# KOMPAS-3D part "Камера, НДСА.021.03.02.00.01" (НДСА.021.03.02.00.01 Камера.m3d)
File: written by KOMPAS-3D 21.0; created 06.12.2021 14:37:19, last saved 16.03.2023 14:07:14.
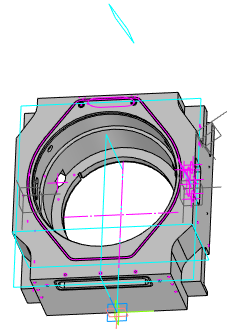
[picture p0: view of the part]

Document properties: Полное имя файла: C:\Users\korychko\Desktop\PLM\НДСА.021.03.02.00.01 Камера.m3d

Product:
- Part/product: Камера  | designation НДСА.021.03.02.00.01
    Материал: АМг6  ГОСТ 4784-2019 (density 2640 kg/m3)
    Масса: 77.159778
    additional columns: <item xmlns="http://appius.ru/pdm" xmlns:xs="http://www.w3.org/2001/XMLSchema" x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; <item xmlns="http://appius.ru/pdm" xmlns:xs="http://www.w3.org/2001/XMLSchema" x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; <item xmlns="http://appius.ru/pdm" xmlns:xs="http://www.w3.org/2001/XMLSchema" x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
    source file: НДСА.021.03.02.00.01 Камера.cdw

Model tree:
1. Эскиз:1
2. Элемент выдавливания:1
     Расстояние 1 = 232
3. Эскиз:2  (with: Элемент выдавливания:1)
4. Элемент выдавливания:2
     Расстояние 2 = 9
5. Эскиз:3  (with: Элемент выдавливания:2)
6. Элемент выдавливания:3
     Расстояние 2 = 75
7. Эскиз:4  (with: Элемент выдавливания:3)
8. Элемент выдавливания:4
     Расстояние 2 = 118
9. Эскиз:5  (with: Элемент выдавливания:4)
10. Элемент выдавливания:5
     Расстояние 2 = 30
11. Средняя плоскость:1  (with: Элемент выдавливания:1)
12. Эскиз:9  (with: Элемент выдавливания:1)
13. Элемент выдавливания:7
     Расстояние 2 = 159
14. Эскиз:11  (with: Элемент выдавливания:1)
15. Элемент выдавливания:8
     Расстояние 2 = 70
16. Эскиз:12  (with: Элемент выдавливания:1, Элемент выдавливания:8, Элемент выдавливания:5)
17. Отверстие:10  (with: Элемент выдавливания:1)  (labels: M6)
     Глубина выреза = 15; Диаметр отверстия = 4.91747; Угол конуса дна = 118; Расстояние 1 = 27.9101; Расстояние 2 = 119.75
18. M6  (with: Элемент выдавливания:1)  (labels: M6; cil0_24705-2004 coarse)
     Длина резьбы = 10; Шаг резьбы = 1; Номинальный диаметр резьбы = 6
19. Массив по концентрической сетке:1  (with: Отверстие:10)  (labels: M6)  (2 pattern instances)
20. Отверстие:10  (labels: M6)
21. Зеркальный массив:1
22. Экземпляр ( 1 )
23. Экземпляр ( 2 )  (with: Массив по концентрической сетке:1, Экземпляр ( 1 ), Отверстие:10)
24. Экземпляр ( 2 )  (with: Отверстие:10)
25. Экземпляр ( 3 )  (with: Отверстие:10)
26. Эскиз:16  (with: Элемент выдавливания:1, Элемент выдавливания:7)
27. Отверстие:13  (with: Элемент выдавливания:1)  (labels: M8)
     Глубина выреза = 20; Диаметр отверстия = 6.64684; Угол конуса дна = 118; Расстояние 1 = 212; Расстояние 2 = 419
28. M8  (with: Элемент выдавливания:1)  (labels: cil0_24705-2004 coarse)
     Длина резьбы = 15; Шаг резьбы = 1.25; Номинальный диаметр резьбы = 8
29. Отверстие:14  (with: Элемент выдавливания:1, M8)  (labels: M8; cil0_24705-2004 coarse)
     Глубина выреза = 20; Диаметр отверстия = 6.64684; Угол конуса дна = 118; Расстояние 1 = 164; Расстояние 2 = 419; Длина резьбы = 15; Шаг резьбы = 1.25; Номинальный диаметр резьбы = 8
30. Отверстие:15  (with: Элемент выдавливания:1, M8)  (labels: M8; cil0_24705-2004 coarse)
     Глубина выреза = 20; Диаметр отверстия = 6.64684; Угол конуса дна = 118; Расстояние 1 = 116; Расстояние 2 = 419; Длина резьбы = 15; Шаг резьбы = 1.25; Номинальный диаметр резьбы = 8
31. Зеркальный массив:3  (with: Экземпляр ( 1 ), Экземпляр ( 2 ), Отверстие:13)
32. Отверстие:14
33. Отверстие:15
34. Эскиз:17  (with: Элемент выдавливания:1, Элемент выдавливания:7)
35. Эскиз:18  (with: Элемент выдавливания:1)
36. Элемент выдавливания:11
     Расстояние 2 = 20
37. Эскиз:19  (with: Элемент выдавливания:11)
38. Отверстие:16  (with: Элемент выдавливания:11)  (labels: M10)
     Глубина выреза = 26; Диаметр отверстия = 8.3762; Угол конуса дна = 118; Расстояние 1 = -30; Расстояние 2 = 95
39. M10  (with: Элемент выдавливания:11)  (labels: cil0_24705-2004 coarse)
     Длина резьбы = 20; Шаг резьбы = 1.5; Номинальный диаметр резьбы = 10
40. Отверстие:17  (with: Элемент выдавливания:11, M10)  (labels: M10; cil0_24705-2004 coarse)
     Глубина выреза = 26; Диаметр отверстия = 8.3762; Угол конуса дна = 118; Расстояние 1 = -30; Расстояние 2 = 13; Длина резьбы = 20; Шаг резьбы = 1.5; Номинальный диаметр резьбы = 10
41. Зеркальный массив:4  (with: Экземпляр ( 1 ), Экземпляр ( 2 ), Элемент выдавливания:11, Отверстие:16)
42. Отверстие:17
43. Сечение:3
44. Смещенная плоскость:1  (with: Элемент выдавливания:1)
     Расстояние = -44
45. Эскиз:21
46. Эскиз:22  (with: Элемент выдавливания:1)
47. Эскиз:23  (with: Элемент выдавливания:1, Элемент выдавливания:7)
48. Элемент выдавливания:12
     Расстояние 2 = 10
49. Эскиз:24  (with: Элемент выдавливания:1)
50. Смещенная плоскость:2  (with: Элемент выдавливания:1)
     Расстояние = -140
51. Эскиз:31  (with: Элемент выдавливания:1)
52. Элемент выдавливания:16
     Расстояние 2 = 232
53. Эскиз:32  (with: Элемент выдавливания:1)
54. Элемент выдавливания:17
     Расстояние 2 = 140
55. Эскиз:33  (with: Элемент выдавливания:1)
56. Эскиз:34
57. Элемент по траектории:3
58. Эскиз:35  (with: Элемент выдавливания:1)
59. Отверстие:20  (with: Элемент выдавливания:1)
     Глубина выреза = 27; Диаметр отверстия = 4.5; Угол конуса дна = 118; Расстояние 1 = 216.5; Расстояние 2 = 198
60. Отверстие:21  (with: Элемент выдавливания:1)  (labels: M3)
     Глубина выреза = 14; Диаметр отверстия = 2.45873; Угол конуса дна = 118; Расстояние 1 = 224.5; Расстояние 2 = 206
61. M3  (with: Элемент выдавливания:1)  (labels: M3; cil0_24705-2004 coarse)
     Длина резьбы = 10; Шаг резьбы = 0.5; Номинальный диаметр резьбы = 3
62. Отверстие:22  (with: Элемент выдавливания:1, M3)  (labels: M3; cil0_24705-2004 coarse)
     Глубина выреза = 14; Диаметр отверстия = 2.45873; Угол конуса дна = 118; Расстояние 1 = 208.5; Расстояние 2 = 206; Длина резьбы = 10; Шаг резьбы = 0.5; Номинальный диаметр резьбы = 3
63. Отверстие:23  (with: Элемент выдавливания:1, M3)  (labels: M3; cil0_24705-2004 coarse)
     Глубина выреза = 14; Диаметр отверстия = 2.45873; Угол конуса дна = 118; Расстояние 1 = 224.5; Расстояние 2 = 190; Длина резьбы = 10; Шаг резьбы = 0.5; Номинальный диаметр резьбы = 3
64. Отверстие:24  (with: Элемент выдавливания:1, M3)  (labels: M3; cil0_24705-2004 coarse)
     Глубина выреза = 14; Диаметр отверстия = 2.45873; Угол конуса дна = 118; Расстояние 1 = 208.5; Расстояние 2 = 190; Длина резьбы = 10; Шаг резьбы = 0.5; Номинальный диаметр резьбы = 3
65. Зеркальный массив:6  (with: Экземпляр ( 1 ), Экземпляр ( 2 ), Отверстие:20, Отверстие:21)
66. Отверстие:22
67. Отверстие:23
68. Отверстие:24
69. Эскиз:36  (with: Элемент выдавливания:1)
70. Элемент выдавливания:18
     Расстояние 2 = 2.5; Угол 2 = 24
71. Скругление:12  (with: Элемент выдавливания:18)
     Радиус = 0.8
72. Скругление:13  (with: Элемент выдавливания:18)
     Радиус = 0.25
73. Эскиз:37  (with: Элемент выдавливания:1, Скругление:13)
74. Отверстие:25  (with: Элемент выдавливания:1)
     Глубина выреза = 18; Диаметр отверстия = 4.5; Угол конуса дна = 118; Расстояние 1 = -70; Расстояние 2 = -497
75. Отверстие:26  (with: Элемент выдавливания:1)
     Глубина выреза = 18; Диаметр отверстия = 4.5; Угол конуса дна = 118; Расстояние 1 = 70; Расстояние 2 = -497
76. Эскиз:38  (with: Элемент выдавливания:1)
77. Элемент выдавливания:19
     Расстояние 2 = 14
78. Эскиз:39  (with: Элемент выдавливания:1)
79. Элемент выдавливания:20
     Расстояние 2 = 24
80. Эскиз:40  (with: Элемент выдавливания:1)
81. Элемент выдавливания:21  (with: Элемент выдавливания:3)
     Расстояние 2 = 50
82. Эскиз:41  (with: Элемент выдавливания:19)
83. Отверстие:27  (with: Элемент выдавливания:19)  (labels: M5)
     Глубина выреза = 14; Диаметр отверстия = 4.13397; Угол конуса дна = 118; Расстояние 1 = 104; Расстояние 2 = 37
84. M5  (with: Элемент выдавливания:19)  (labels: cil0_24705-2004 coarse)
     Длина резьбы = 10; Шаг резьбы = 0.8; Номинальный диаметр резьбы = 5
85. Отверстие:28  (with: Элемент выдавливания:19, M5)  (labels: M5; cil0_24705-2004 coarse)
     Глубина выреза = 14; Диаметр отверстия = 4.13397; Угол конуса дна = 118; Расстояние 1 = 75; Расстояние 2 = 6; Длина резьбы = 10; Шаг резьбы = 0.8; Номинальный диаметр резьбы = 5
86. Отверстие:29  (with: Элемент выдавливания:19, M5)  (labels: M5; cil0_24705-2004 coarse)
     Глубина выреза = 14; Диаметр отверстия = 4.13397; Угол конуса дна = 118; Расстояние 1 = 35; Расстояние 2 = 6; Длина резьбы = 10; Шаг резьбы = 0.8; Номинальный диаметр резьбы = 5
87. Отверстие:30  (with: Элемент выдавливания:19, M5)  (labels: M5; cil0_24705-2004 coarse)
     Глубина выреза = 14; Диаметр отверстия = 4.13397; Угол конуса дна = 118; Расстояние 1 = 6; Расстояние 2 = 37; Длина резьбы = 10; Шаг резьбы = 0.8; Номинальный диаметр резьбы = 5
88. Отверстие:31  (with: Элемент выдавливания:19, M5)  (labels: M5; cil0_24705-2004 coarse)
     Глубина выреза = 14; Диаметр отверстия = 4.13397; Угол конуса дна = 118; Расстояние 1 = 35; Расстояние 2 = 68; Длина резьбы = 10; Шаг резьбы = 0.8; Номинальный диаметр резьбы = 5
89. Отверстие:32  (with: Элемент выдавливания:19, M5)  (labels: M5; cil0_24705-2004 coarse)
     Глубина выреза = 14; Диаметр отверстия = 4.13397; Угол конуса дна = 118; Расстояние 1 = 75; Расстояние 2 = 68; Длина резьбы = 10; Шаг резьбы = 0.8; Номинальный диаметр резьбы = 5
90. Эскиз:42  (with: Элемент выдавливания:20)
91. Эскиз:43
92. Элемент по траектории:4
93. Зеркальный массив:7  (with: Экземпляр ( 1 ), Экземпляр ( 2 ), Элемент выдавливания:19, Элемент выдавливания:20, Элемент выдавливания:21, Отверстие:27)
94. Отверстие:28
95. Отверстие:29
96. Отверстие:30
97. Отверстие:31
98. Отверстие:32
99. Элемент по траектории:4
100. Эскиз:44  (with: Элемент выдавливания:1)
101. Отверстие:33  (with: Элемент выдавливания:1, Элемент выдавливания:17, M8)  (labels: M8; cil0_24705-2004 coarse)
     Глубина выреза = 15; Диаметр отверстия = 6.64684; Угол конуса дна = 118; Расстояние 1 = 145.841; Расстояние 2 = 333.75; Длина резьбы = 12; Шаг резьбы = 1.25; Номинальный диаметр резьбы = 8
102. Отверстие:34  (with: Элемент выдавливания:1, Элемент выдавливания:17, M8)  (labels: M8; cil0_24705-2004 coarse)
     Глубина выреза = 15; Диаметр отверстия = 6.64684; Угол конуса дна = 118; Расстояние 1 = 79.5495; Расстояние 2 = 240; Длина резьбы = 12; Шаг резьбы = 1.25; Номинальный диаметр резьбы = 8
103. Отверстие:35  (with: Элемент выдавливания:1, Элемент выдавливания:17, M8)  (labels: M8; cil0_24705-2004 coarse)
     Глубина выреза = 15; Диаметр отверстия = 6.64684; Угол конуса дна = 118; Расстояние 1 = 13.2583; Расстояние 2 = 146.25; Длина резьбы = 12; Шаг резьбы = 1.25; Номинальный диаметр резьбы = 8
104. Эскиз:45  (with: Элемент выдавливания:1)
105. Элемент выдавливания:22  (with: Элемент выдавливания:1)
     Расстояние 2 = 232
106. Эскиз:46  (with: Элемент выдавливания:1)
107. Элемент выдавливания:23
     Расстояние 2 = 92
108. Эскиз:47  (with: Элемент выдавливания:1, Элемент выдавливания:23)
109. Эскиз:48  (with: Элемент выдавливания:1)
110. Элемент выдавливания:24
     Расстояние 2 = 70
111. Элемент выдавливания:25
     Расстояние 2 = 100
112. Эскиз:49  (with: Элемент выдавливания:25, Элемент выдавливания:3)
113. Отверстие:36  (with: Элемент выдавливания:25, Элемент выдавливания:24, M10)  (labels: M10; cil0_24705-2004 coarse)
     Глубина выреза = 20; Диаметр отверстия = 8.3762; Угол конуса дна = 118; Расстояние 1 = 75; Расстояние 2 = 35; Длина резьбы = 15; Шаг резьбы = 1.5; Номинальный диаметр резьбы = 10
114. Отверстие:37  (with: Элемент выдавливания:25, Элемент выдавливания:24, M10)  (labels: M10; cil0_24705-2004 coarse)
     Глубина выреза = 20; Диаметр отверстия = 8.3762; Угол конуса дна = 118; Расстояние 1 = 25; Расстояние 2 = 35; Длина резьбы = 15; Шаг резьбы = 1.5; Номинальный диаметр резьбы = 10
115. Зеркальный массив:8  (with: Экземпляр ( 1 ), Экземпляр ( 2 ), Отверстие:36)
116. Отверстие:37
117. Скругление:14  (with: Элемент выдавливания:25)
     Радиус = 5
118. Эскиз:50  (with: Элемент выдавливания:1, Элемент выдавливания:24)
119. Отверстие:38  (with: Элемент выдавливания:1, Элемент выдавливания:25, Элемент выдавливания:24, M5)  (labels: M5; cil0_24705-2004 coarse)
     Глубина выреза = 16; Диаметр отверстия = 4.13397; Угол конуса дна = 118; Расстояние 1 = 32.5; Расстояние 2 = -10; Длина резьбы = 12; Шаг резьбы = 0.8; Номинальный диаметр резьбы = 5
120. Отверстие:39  (with: Элемент выдавливания:1, Элемент выдавливания:25, Элемент выдавливания:24, M5)  (labels: M5; cil0_24705-2004 coarse)
     Глубина выреза = 16; Диаметр отверстия = 4.13397; Угол конуса дна = 118; Расстояние 1 = 166.5; Расстояние 2 = -10; Длина резьбы = 12; Шаг резьбы = 0.8; Номинальный диаметр резьбы = 5
121. Зеркальный массив:9  (with: Экземпляр ( 1 ), Экземпляр ( 2 ), Отверстие:38)
122. Отверстие:39
123. Эскиз:51  (with: Элемент выдавливания:1)
124. Отверстие:40  (with: Элемент выдавливания:1, Элемент выдавливания:24, M5)  (labels: M5; cil0_24705-2004 coarse)
     Глубина выреза = 16; Диаметр отверстия = 4.13397; Угол конуса дна = 118; Расстояние 1 = 57.5; Расстояние 2 = -344; Длина резьбы = 12; Шаг резьбы = 0.8; Номинальный диаметр резьбы = 5
125. Отверстие:41  (with: Элемент выдавливания:1, Элемент выдавливания:24, M5)  (labels: M5; cil0_24705-2004 coarse)
     Глубина выреза = 16; Диаметр отверстия = 4.13397; Угол конуса дна = 118; Расстояние 1 = -92.5; Расстояние 2 = -344; Длина резьбы = 12; Шаг резьбы = 0.8; Номинальный диаметр резьбы = 5
126. Зеркальный массив:10  (with: Экземпляр ( 1 ), Экземпляр ( 2 ), Отверстие:41)
127. Отверстие:40
128. Эскиз:52  (with: Элемент выдавливания:1, Элемент по траектории:3)
129. Элемент выдавливания:26
     Расстояние 2 = 10
130. Эскиз:61  (with: Элемент выдавливания:1, Элемент выдавливания:26)
131. ЛСК:7  (with: Плоскость XY, Плоскость ZX, Плоскость ZY, Ось X, Ось Y, Ось Z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)
     Ось X. Z = 1; Ось Y. X = 1; Ось Z. Y = 1; Координата X = -243.145; Координата Y = 214.688; Координата Z = 232; Точка начала. Х = -243.145; Точка начала. Y = 214.688; Точка начала. Z = 232
132. Эскиз:62
133. Элемент вращения:3
     Угол 1 = 360
134. Отверстие Ф5x11
135. Эскиз:64  (with: Элемент выдавливания:1, Элемент выдавливания:26)
136. ЛСК:9  (with: Плоскость XY, Плоскость ZX, Плоскость ZY, Ось X, Ось Y, Ось Z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)
     Ось X. Z = 1; Ось Y. X = 1; Ось Z. Y = 1; Координата X = -243.145; Координата Y = -214.688; Координата Z = 232; Точка начала. Х = -243.145; Точка начала. Y = -214.688; Точка начала. Z = 232
137. Эскиз:65
138. Элемент вращения:4
     Угол 1 = 360
139. Отверстие Ф5x11 (1)
140. Эскиз:66  (with: Элемент выдавливания:23)
141. Элемент выдавливания:27
     Расстояние 2 = 100
142. Эскиз:67  (with: Элемент выдавливания:23, Элемент выдавливания:27)
143. Элемент выдавливания:28
     Расстояние 2 = 9.7
144. Эскиз:68  (with: Элемент выдавливания:23, Элемент выдавливания:28)
145. Элемент выдавливания:29
     Расстояние 2 = 3
146. Эскиз:70  (with: Элемент выдавливания:23, Элемент выдавливания:29)
147. ЛСК:11  (with: Плоскость XY, Плоскость ZX, Плоскость ZY, Ось X, Ось Y, Ось Z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)
     Ось X. X = -0.573576; Ось X. Y = 0.819152; Ось Y. X = 0.819152; Ось Y. Y = 0.573576; Ось Z. Z = -1; Координата X = -424.863; Координата Y = 228.893; Координата Z = 184.565; Точка начала. Х = -424.863; Точка начала. Y = 228.893; Точка начала. Z = 184.565
148. Эскиз:71
149. Элемент вращения:5
     Угол 1 = 360
150. Смещенная плоскость:3  (with: Элемент выдавливания:23)
151. Условное изображение резьбы:1  (with: Элемент вращения:5)  (labels: 4x0,699999)
     Длина резьбы = 8; Шаг резьбы = 0.7; Номинальный диаметр резьбы = 4
152. Подгонка:1
153. Отверстие М4x8-12
154. Массив по концентрической сетке:3  (with: Элемент вращения:5)  (2 pattern instances)
155. Элемент вращения:5
156. Элемент вращения:5
157. Зеркальный массив:11  (with: Экземпляр ( 1 ), Экземпляр ( 2 ), Элемент выдавливания:27, Элемент выдавливания:28, Элемент выдавливания:29, Массив по концентрической сетке:3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)
158. Экземпляр ( 2 )  (with: Элемент вращения:5)
159. Экземпляр ( 3 )  (with: Элемент вращения:5)
160. Экземпляр ( 4 )  (with: Элемент вращения:5)
161. Скругление:15  (with: Элемент выдавливания:27)
     Радиус = 4
162. Скругление:16  (with: Элемент выдавливания:23)
     Радиус = 50
163. Эскиз:72  (with: Элемент выдавливания:1)
164. Элемент выдавливания:30
     Расстояние 2 = 0.01
165. Эскиз:73  (with: Элемент выдавливания:1, Элемент выдавливания:5)
166. Элемент выдавливания:31
     Расстояние 1 = 2
167. Нормальная плоскость:1  (with: Элемент выдавливания:8)
     Угол = -30
168. Эскиз:74  (with: Элемент выдавливания:8)
169. Эскиз:77  (with: Элемент выдавливания:4, Элемент выдавливания:5)
170. Элемент выдавливания:34
     Расстояние 2 = 32
171. Фаска:1  (with: Элемент выдавливания:34)  (labels: АМг6  ГОСТ 4784-2019)
     Угол = 45; Длина 1 = 1; Длина 2 = 1

Referenced files in C:\Users\korychko\Desktop\PLM\: НДСА.021.03.00.00.00 Модуль процессный.a3d
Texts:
  Body Specification ( left align )
  Body Specificaton ( centered )
  KTE.LIST=n_PfPiM9npJc1b4JNb1Maa
  KTE.LIST=N.JCFQmPcnMVtYB9e4EPvb
  Edge1
  Edge2
  Центр круглого ребра
  НДСА.021.03.02.00.01
  Шаг 1
  Режим 1
  Шаг 2
  Режим 2
  Шаг по оси
  Номер 1
  Номер 2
